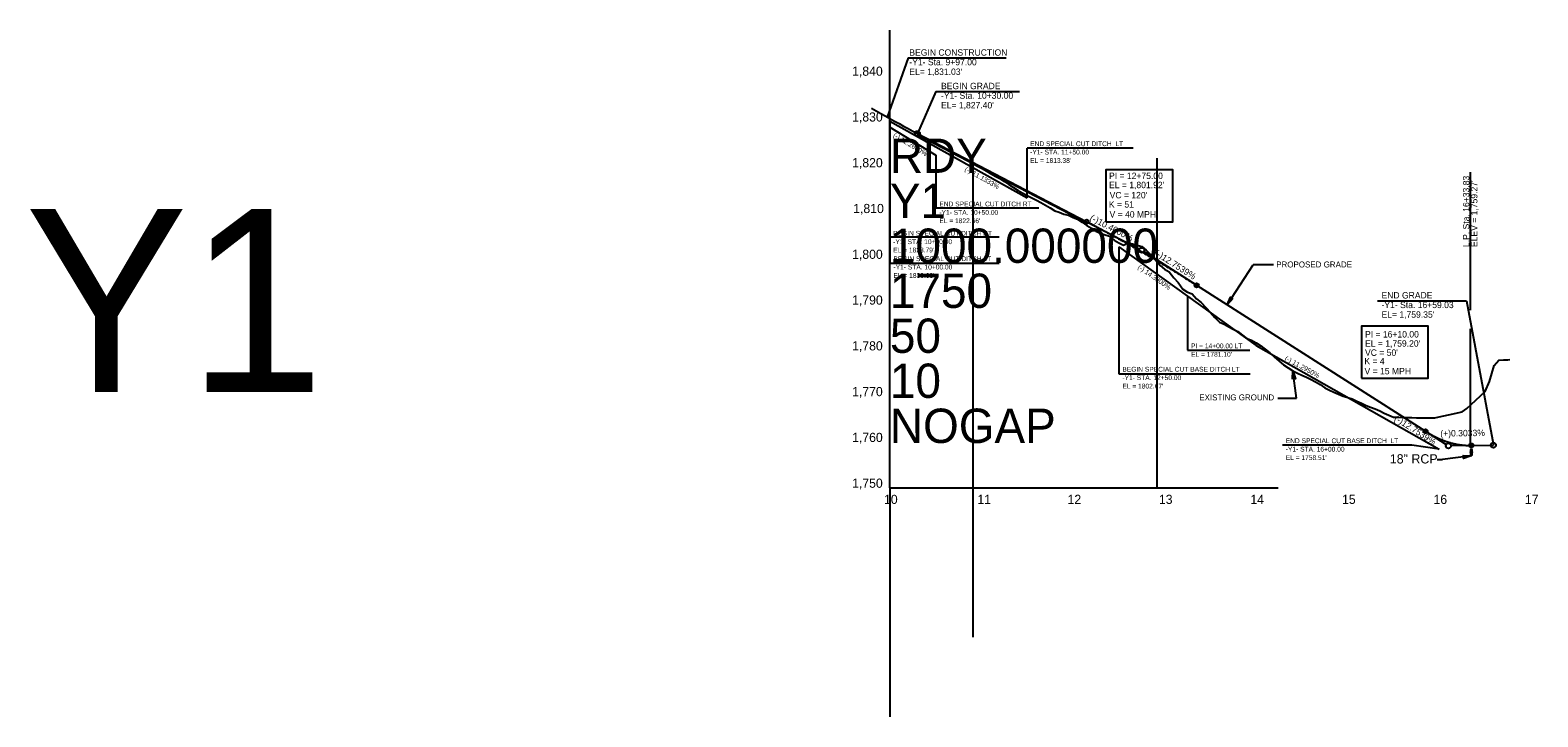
# Model space of a CAD drawing. Extents: x 498575 to 532350, y 405181 to 484585.
# Drawn here: x 504918 to 506564, y 480069 to 480819 of the extents above; entities that cross this region are included whole.
import ezdxf

# ---------------------------------------------------------------- set-up
doc = ezdxf.new("R2010")
doc.units = 0
for name, color, linetype in [('Exist Profile Cell', 7, 'Continuous'), ('Exist Vertical Profile Ground Line', 7, 'Continuous'), ('Exist Vertical Profile Horizontal Axis Label Major', 7, 'Continuous'), ('Exist Vertical Profile Vertical Axis Label', 7, 'Continuous'), ('Prop Drainage Structure Pipe Welded Steel 54in Label', 7, 'Continuous'), ('Prop Grid Mask', 7, 'Continuous'), ('Prop PFL Text', 7, 'Continuous'), ('Prop Vertical Profile Curve Label', 7, 'Continuous'), ('Prop Vertical Profile Ditch Grade Left', 7, 'Continuous'), ('Prop Vertical Profile Ditch Grade Left Label', 7, 'Continuous'), ('Prop Vertical Profile Ditch Grade Right', 7, 'Continuous'), ('Prop Vertical Profile Ditch Grade Right Label', 7, 'Continuous'), ('Prop Vertical Profile Grade', 7, 'Continuous'), ('Prop Vertical Profile Grade Label', 7, 'Continuous'), ('Prop Vertical Profile Strip Grade', 7, 'Continuous'), ('Prop VPI Label', 7, 'Continuous'), ('Scratch_Level_5', 7, 'Continuous'), ('Scratch_Level_7', 7, 'Continuous'), ('Scratch_Level_8', 7, 'Continuous')]:
    doc.layers.add(name, color=color, linetype=linetype)

msp = doc.modelspace()

# ---------------------------------------------------------------- linework, layer by layer
at = {"layer": 'Exist Profile Cell'}
for q in [(505856.7, 480819.3), (506280.6, 480319.3), (505856.7, 480069.3)]:
    msp.add_line((505856.7, 480319.3), q, dxfattribs=at)
at = {"layer": 'Exist Vertical Profile Ground Line'}
for points in [[(505836.7, 480734.1), (505841.7, 480731.3), (505846.7, 480728.4), (505851.7, 480725.6), (505856.7, 480722.7), (505861.7, 480720), (505866.7, 480717.2), (505871.7, 480714.5), (505876.7, 480711.8), (505881.7, 480709), (505886.7, 480706.3), (505891.7, 480703.6), (505896.7, 480700.9), (505901.7, 480698.3), (505906.7, 480695.7), (505911.7, 480693), (505916.7, 480690.3), (505921.7, 480687.5), (505926.7, 480684.8), (505931.7, 480682.1), (505936.7, 480679.3), (505941.7, 480676.7), (505946.7, 480673.9), (505951.7, 480671.1), (505956.7, 480668.4), (505961.7, 480665.6), (505966.7, 480662.8), (505971.7, 480659.9), (505976.7, 480657.1), (505981.7, 480654.1), (505986.7, 480650.8), (505991.7, 480647.4), (505996.7, 480644.3), (506001.7, 480641.4), (506006.7, 480638.6), (506011.7, 480636), (506016.7, 480633.5), (506021.7, 480630.9), (506026.7, 480628.1), (506031.7, 480625.1), (506036.7, 480622), (506041.7, 480620.6), (506046.7, 480618.2), (506051.7, 480617.3), (506056.7, 480614.8), (506061.7, 480613), (506066.7, 480609.5), (506071.7, 480606), (506076.7, 480603.1), (506081.7, 480599.8), (506086.7, 480597.7), (506091.7, 480595.6), (506096.7, 480594.2), (506101.7, 480589.8), (506106.7, 480587.1), (506111.7, 480584.6), (506116.7, 480587), (506121.7, 480585.8), (506126.7, 480584.6), (506131.7, 480583), (506136.7, 480579), (506141.7, 480573.8), (506146.7, 480568.3), (506151.7, 480562.4), (506156.7, 480558.3), (506161.7, 480555.4), (506166.7, 480548.6), (506171.7, 480543.8), (506176.7, 480536.3), (506181.7, 480533.2), (506186.7, 480531.2), (506191.7, 480526), (506196.7, 480522), (506201.7, 480516.4), (506206.7, 480510.9), (506211.7, 480505.5), (506216.7, 480500.5), (506221.7, 480498.1), (506226.7, 480495.4), (506231.7, 480492.8), (506236.7, 480490.1), (506241.7, 480486.3), (506246.7, 480482.6), (506251.7, 480480.8), (506256.7, 480477.9), (506261.7, 480474.4), (506266.7, 480470.9), (506271.7, 480466.7), (506276.7, 480462.3), (506281.7, 480457.8), (506286.7, 480453.9), (506291.7, 480450.5), (506296.7, 480447.1), (506301.7, 480444.6), (506306.7, 480442.5), (506311.7, 480440.3), (506316.7, 480437.7), (506321.7, 480435.2), (506326.7, 480432.1), (506331.7, 480428.7), (506336.7, 480426)], [(506336.7, 480426), (506341.7, 480424), (506346.7, 480421.8), (506351.7, 480419.6), (506356.7, 480418.2), (506361.7, 480416.6), (506366.7, 480414.1), (506371.7, 480411.8), (506376.7, 480409.4), (506381.7, 480407.6), (506386.7, 480405.8), (506391.7, 480403.6), (506396.7, 480401.1), (506401.7, 480398.6), (506406.7, 480396.7), (506411.7, 480396.5), (506416.7, 480396.4), (506421.7, 480396.3), (506426.7, 480396.2), (506431.7, 480396), (506436.7, 480395.9), (506441.7, 480395.8), (506446.7, 480395.7), (506451.7, 480395.8), (506456.7, 480396.9), (506461.7, 480398.1), (506466.7, 480399.3), (506471.7, 480400.3), (506476.7, 480401.4), (506481.7, 480402.5), (506486.7, 480406), (506491.7, 480410.6), (506496.7, 480415.2), (506501.7, 480419.8), (506506.7, 480424.7), (506511.7, 480435.6), (506516.7, 480453.2), (506521.7, 480458.9), (506526.7, 480459.1), (506531.7, 480459.3), (506533.8, 480459.5)]]:
    msp.add_lwpolyline(points, dxfattribs=at)
at = {"layer": 'Prop Drainage Structure Pipe Welded Steel 54in Label'}
for p in [(506491.7, 480354.4), (506454.5, 480350.2)]:
    msp.add_line(p, (506460.4, 480350.2), dxfattribs=at)
msp.add_lwpolyline([(506482.6, 480354.7), (506491.7, 480354.4), (506483, 480351.6), (506483.9, 480353.4)], close=True, dxfattribs=at)
msp.add_ellipse((506491.7, 480358.2), major_axis=(0, 3.75), ratio=0.2, dxfattribs=at)
at = {"layer": 'Prop Grid Mask'}
for points in [[(506092.7, 480610.1), (506165.7, 480610.1), (506165.7, 480666.9), (506092.7, 480666.9)], [(506371.7, 480439.2), (506444.7, 480439.2), (506444.7, 480496), (506371.7, 480496)]]:
    msp.add_lwpolyline(points, close=True, dxfattribs=at)
at = {"layer": 'Prop PFL Text'}
for p, q in [((506225.2, 480519.3), (506253.3, 480563.1)), ((506275.6, 480563.1), (506253.3, 480563.1)), ((506300.9, 480417.5), (506296.7, 480447.1)), ((506280.5, 480417.5), (506300.9, 480417.5))]:
    msp.add_line(p, q, dxfattribs=at)
for points in [[(506231.3, 480526.1), (506225.2, 480519.3), (506228.7, 480527.8), (506229.4, 480526)], [(506296.5, 480438), (506296.7, 480447.1), (506299.6, 480438.3), (506297.8, 480439.3)]]:
    msp.add_lwpolyline(points, close=True, dxfattribs=at)
at = {"layer": 'Prop Vertical Profile Curve Label'}
for centre in [(506071.7, 480610.1), (506191.7, 480540.6), (506441.7, 480381.2), (506491.7, 480365.7)]:
    msp.add_circle(centre, 2.25, dxfattribs=at)
at = {"layer": 'Prop Vertical Profile Ditch Grade Left'}
for points in [[(505856.7, 480719.7), (506006.7, 480636.2)], [(506106.7, 480582.6), (506256.7, 480474.8), (506456.7, 480361.8)]]:
    msp.add_lwpolyline(points, dxfattribs=at)
at = {"layer": 'Prop Vertical Profile Ditch Grade Left Label'}
for p, q in [((505856.7, 480719.7), (505856.7, 480564.9)), ((506006.7, 480636.2), (506006.7, 480690.5)), ((506122.5, 480690.5), (506006.7, 480690.5)), ((506106.7, 480582.6), (506106.7, 480444.1)), ((505856.7, 480564.9), (505975.9, 480564.9)), ((506181.7, 480528.7), (506181.7, 480469.6)), ((506181.7, 480469.6), (506249.7, 480469.6)), ((506106.7, 480444.1), (506250.2, 480444.1)), ((506426.7, 480366.1), (506285.5, 480366.1)), ((506456.7, 480361.8), (506426.7, 480366.1))]:
    msp.add_line(p, q, dxfattribs=at)
at = {"layer": 'Prop Vertical Profile Ditch Grade Right'}
msp.add_lwpolyline([(505856.7, 480713.2), (505906.7, 480682.6)], dxfattribs=at)
at = {"layer": 'Prop Vertical Profile Ditch Grade Right Label'}
for p, q in [((505856.7, 480713.2), (505856.7, 480593.2)), ((505906.7, 480682.6), (505906.7, 480625)), ((506019.3, 480625), (505906.7, 480625)), ((505976.2, 480593.2), (505856.7, 480593.2))]:
    msp.add_line(p, q, dxfattribs=at)
at = {"layer": 'Prop Vertical Profile Grade'}
for p, q in [((505886.7, 480706.3), (506071.7, 480610.1)), ((506191.7, 480540.6), (506441.7, 480381.2)), ((506491.7, 480365.7), (506515.8, 480366))]:
    msp.add_line(p, q, dxfattribs=at)
for points in [[(506071.7, 480610.1), (506074.1, 480608.9), (506076.5, 480607.6), (506078.9, 480606.3), (506081.3, 480605.1), (506083.7, 480603.8), (506086.1, 480602.5), (506088.5, 480601.2), (506090.9, 480599.9), (506093.3, 480598.6), (506095.7, 480597.3), (506098.1, 480596), (506100.5, 480594.7), (506102.9, 480593.4), (506105.3, 480592.1), (506107.7, 480590.7), (506110.1, 480589.4), (506112.5, 480588.1), (506114.9, 480586.7), (506117.3, 480585.4), (506119.7, 480584), (506122.1, 480582.7), (506124.5, 480581.3), (506126.9, 480579.9), (506129.3, 480578.5), (506131.7, 480577.1), (506134.1, 480575.7), (506136.5, 480574.3), (506138.9, 480572.9), (506141.3, 480571.5), (506143.7, 480570.1), (506146.1, 480568.7), (506148.5, 480567.3), (506150.9, 480565.8), (506153.3, 480564.4), (506155.7, 480563), (506158.1, 480561.5), (506160.5, 480560.1), (506162.9, 480558.6), (506165.3, 480557.1), (506167.7, 480555.7), (506170.1, 480554.2), (506172.5, 480552.7), (506174.9, 480551.2), (506177.3, 480549.7), (506179.7, 480548.2), (506182.1, 480546.7), (506184.5, 480545.2), (506186.9, 480543.7), (506189.3, 480542.2), (506191.7, 480540.6)], [(506441.7, 480381.2), (506442.7, 480380.6), (506443.7, 480380), (506444.7, 480379.4), (506445.7, 480378.8), (506446.7, 480378.2), (506447.7, 480377.6), (506448.7, 480377.1), (506449.7, 480376.5), (506450.7, 480376), (506451.7, 480375.5), (506452.7, 480375), (506453.7, 480374.5), (506454.7, 480374), (506455.7, 480373.6), (506456.7, 480373.1), (506457.7, 480372.7), (506458.7, 480372.3), (506459.7, 480371.9), (506460.7, 480371.5), (506461.7, 480371.1), (506462.7, 480370.7), (506463.7, 480370.3), (506464.7, 480370), (506465.7, 480369.7), (506466.7, 480369.4), (506467.7, 480369.1), (506468.7, 480368.8), (506469.7, 480368.5), (506470.7, 480368.2), (506471.7, 480368), (506472.7, 480367.7), (506473.7, 480367.5), (506474.7, 480367.3), (506475.7, 480367.1), (506476.7, 480366.9), (506477.7, 480366.7), (506478.7, 480366.6), (506479.7, 480366.4), (506480.7, 480366.3), (506481.7, 480366.2), (506482.7, 480366), (506483.7, 480366), (506484.7, 480365.9), (506485.7, 480365.8), (506486.7, 480365.7), (506487.7, 480365.7), (506488.7, 480365.7), (506489.7, 480365.7), (506490.7, 480365.6), (506491.7, 480365.7)]]:
    msp.add_spline(points, degree=3, dxfattribs=at)
at = {"layer": 'Prop Vertical Profile Strip Grade'}
for p, q in [((506490.6, 480664.2), (506490.6, 480513.6)), ((506490.6, 480493), (506490.6, 480488.2)), ((506490.6, 480488.2), (506490.6, 480365.6))]:
    msp.add_line(p, q, dxfattribs=at)
at = {"layer": 'Prop VPI Label'}
for p, q in [((505876.8, 480788.9), (505853.7, 480724.4)), ((505876.8, 480788.9), (505983.5, 480788.9)), ((505906.7, 480752.3), (505886.7, 480706.3)), ((505906.7, 480752.3), (505998.1, 480752.3)), ((506071.7, 480610.1), (506129.3, 480580.2)), ((506191.7, 480540.6), (506134.1, 480577.4)), ((506389.2, 480523.6), (506486.5, 480523.6)), ((506486.5, 480523.6), (506515.8, 480366)), ((506441.7, 480381.2), (506464.4, 480366.8)), ((506491.7, 480365.7), (506469.5, 480365.3))]:
    msp.add_line(p, q, dxfattribs=at)
for centre in [(505886.7, 480706.3), (506131.7, 480578.9), (506466.7, 480365.3), (506515.8, 480366)]:
    msp.add_circle(centre, 2.75, dxfattribs=at)
at = {"layer": 'Scratch_Level_5'}
for p, q in [((505886.3, 480705.4), (506071.3, 480609.2)), ((505947.1, 480673.7), (505947.1, 480156.4))]:
    msp.add_line(p, q, dxfattribs=at)
at = {"layer": 'Scratch_Level_8'}
msp.add_line((506148.7, 480319.3), (506148.7, 480679.4), dxfattribs=at)

# ---------------------------------------------------------------- texts
at = {"layer": 'Exist Profile Cell'}
for s, p in [('RDY', (505856.7, 480663.4)), ('Y1', (505856.7, 480614.2)), ('1000.000000', (505856.7, 480565.1)), ('1750', (505856.7, 480515.9)), ('50', (505856.7, 480466.8)), ('10', (505856.7, 480417.6)), ('NOGAP', (505856.7, 480368.4))]:
    msp.add_text(s, height=37.5, dxfattribs=at).set_placement(p)
at = {"layer": 'Exist Vertical Profile Horizontal Axis Label Major'}
for s, p in [('10', (505850.3, 480301.8)), ('11', (505952.2, 480301.8)), ('12', (506050.7, 480301.8)), ('13', (506150.5, 480301.8)), ('14', (506250.4, 480301.8)), ('15', (506350.5, 480301.8)), ('16', (506450.4, 480301.8)), ('17', (506550.2, 480301.8))]:
    msp.add_text(s, height=10, dxfattribs=at).set_placement(p)
at = {"layer": 'Exist Vertical Profile Vertical Axis Label'}
for s, p in [('1,840', (505815.4, 480769.5)), ('1,830', (505815.4, 480719.5)), ('1,820', (505815.4, 480669.5)), ('1,810', (505816.6, 480619.5)), ('1,800', (505815.4, 480569.5)), ('1,790', (505815.4, 480519.5)), ('1,780', (505815.4, 480469.5)), ('1,770', (505815.4, 480419.5)), ('1,760', (505815.4, 480369.5)), ('1,750', (505815.4, 480319.5))]:
    msp.add_text(s, height=10, dxfattribs=at).set_placement(p)
at = {"layer": 'Prop Drainage Structure Pipe Welded Steel 54in Label'}
msp.add_text('18" RCP', height=10.12, dxfattribs=at).set_placement((506402.7, 480346))
at = {"layer": 'Prop PFL Text'}
for s, p in [('PROPOSED GRADE', (506278.6, 480560.1)), ('EXISTING GROUND', (506194.6, 480414.9))]:
    msp.add_text(s, height=6.516, dxfattribs=at).set_placement(p)
at = {"layer": 'Prop Vertical Profile Curve Label'}
for s, p in [('K = 51', (506095.9, 480625.5)), ("VC = 120'", (506096.7, 480635.6)), ('V = 40 MPH', (506096.6, 480614.6)), ("VC = 50'", (506375.6, 480463.6)), ('V = 15 MPH', (506375.1, 480443.4)), ('K = 4', (506374.9, 480454.3))]:
    msp.add_text(s, height=7, dxfattribs=at).set_placement(p)
at = {"layer": 'Prop Vertical Profile Ditch Grade Left Label'}
for s, rotation, p in [('END SPECIAL CUT DITCH  LT', 360, (506009.9, 480692.6)), ('-Y1- STA. 11+50.00', 360, (506009.9, 480683.5)), ('(-) 11.1333%', 330.7723, (505937.8, 480665.9)), ("EL = 1813.38'", 360, (506009.9, 480674.3)), ('BEGIN SPECIAL CUT DITCH LT', 360, (505860.6, 480567)), ('-Y1- STA. 10+00.00', 360, (505860.6, 480557.9)), ("EL = 1830.08'", 360, (505860.6, 480548.7)), ('(-) 14.3800%', 325.2771, (506126.8, 480559.2)), ('PI = 14+00.00 LT', 360, (506185.6, 480471.8)), ("EL = 1781.10'", 360, (506185.6, 480462.6)), ('BEGIN SPECIAL CUT BASE DITCH LT', 360, (506110.6, 480446.3)), ('(-) 11.2950%', 331.4761, (506287.4, 480459.2)), ('-Y1- STA. 12+50.00', 360, (506110.6, 480437.1)), ("EL = 1802.67'", 360, (506110.6, 480427.9)), ('END SPECIAL CUT BASE DITCH  LT', 360, (506289, 480368.2)), ('-Y1- STA. 16+00.00', 360, (506289, 480359)), ("EL = 1758.51'", 360, (506289, 480349.8))]:
    msp.add_text(s, height=5.25, rotation=rotation, dxfattribs=at).set_placement(p)
at = {"layer": 'Prop Vertical Profile Ditch Grade Right Label'}
for s, rotation, p in [('(-) 12.2600%', 328.7982, (505859.6, 480703.1)), ('END SPECIAL CUT DITCH RT', 360, (505910.7, 480626.8)), ('-Y1- STA. 10+50.00', 360, (505910.7, 480617.6)), ('BEGIN SPECIAL CUT DITCH RT', 360, (505860.3, 480594.8)), ("EL = 1822.66'", 360, (505910.7, 480608.5)), ('-Y1- STA. 10+00.00', 360, (505860.3, 480585.6)), ("EL = 1828.79'", 360, (505860.3, 480576.5))]:
    msp.add_text(s, height=5.25, rotation=rotation, dxfattribs=at).set_placement(p)
at = {"layer": 'Prop Vertical Profile Grade Label'}
for s, rotation, p in [('(-)10.4000%', 332.5256, (506074.4, 480612.1)), ('(-)12.7539%', 327.4745, (506144.7, 480574.2)), ('(-)12.7539%', 327.4745, (506406.9, 480393.4)), ('(+)0.3033%', 0.8687, (506457.9, 480375.3))]:
    msp.add_text(s, height=7, rotation=rotation, dxfattribs=at).set_placement(p)
at = {"layer": 'Prop Vertical Profile Strip Grade'}
for s, p in [('L.P. Sta. 16+33.83', (506489.6, 480582.4)), ("ELEV = 1,759.27'", (506498.4, 480582.4))]:
    msp.add_text(s, height=7, rotation=90, dxfattribs=at).set_placement(p)
at = {"layer": 'Prop VPI Label'}
for s, p in [('BEGIN CONSTRUCTION', (505877.9, 480791.4)), ('-Y1- Sta. 9+97.00', (505877.9, 480780.9)), ("EL= 1,831.03'", (505877.9, 480770.4)), ('-Y1- Sta. 10+30.00', (505912.5, 480744.3)), ('BEGIN GRADE', (505912.5, 480754.8)), ("EL= 1,827.40'", (505912.5, 480733.8)), ('PI = 12+75.00', (506096, 480656.7)), ("EL = 1,801.92'", (506096, 480646.7)), ('END GRADE', (506393.6, 480526.2)), ('-Y1- Sta. 16+59.03', (506393.6, 480515.7)), ("EL= 1,759.35'", (506393.6, 480505.2)), ('PI = 16+10.00', (506375.6, 480483.6)), ("EL = 1,759.20'", (506375.6, 480473.6))]:
    msp.add_text(s, height=7, dxfattribs=at).set_placement(p)
at = {"layer": 'Scratch_Level_7'}
msp.add_text('Y1', height=200, dxfattribs=at).set_placement((504911.8, 480423.9))

doc.saveas('drawing.dxf')
